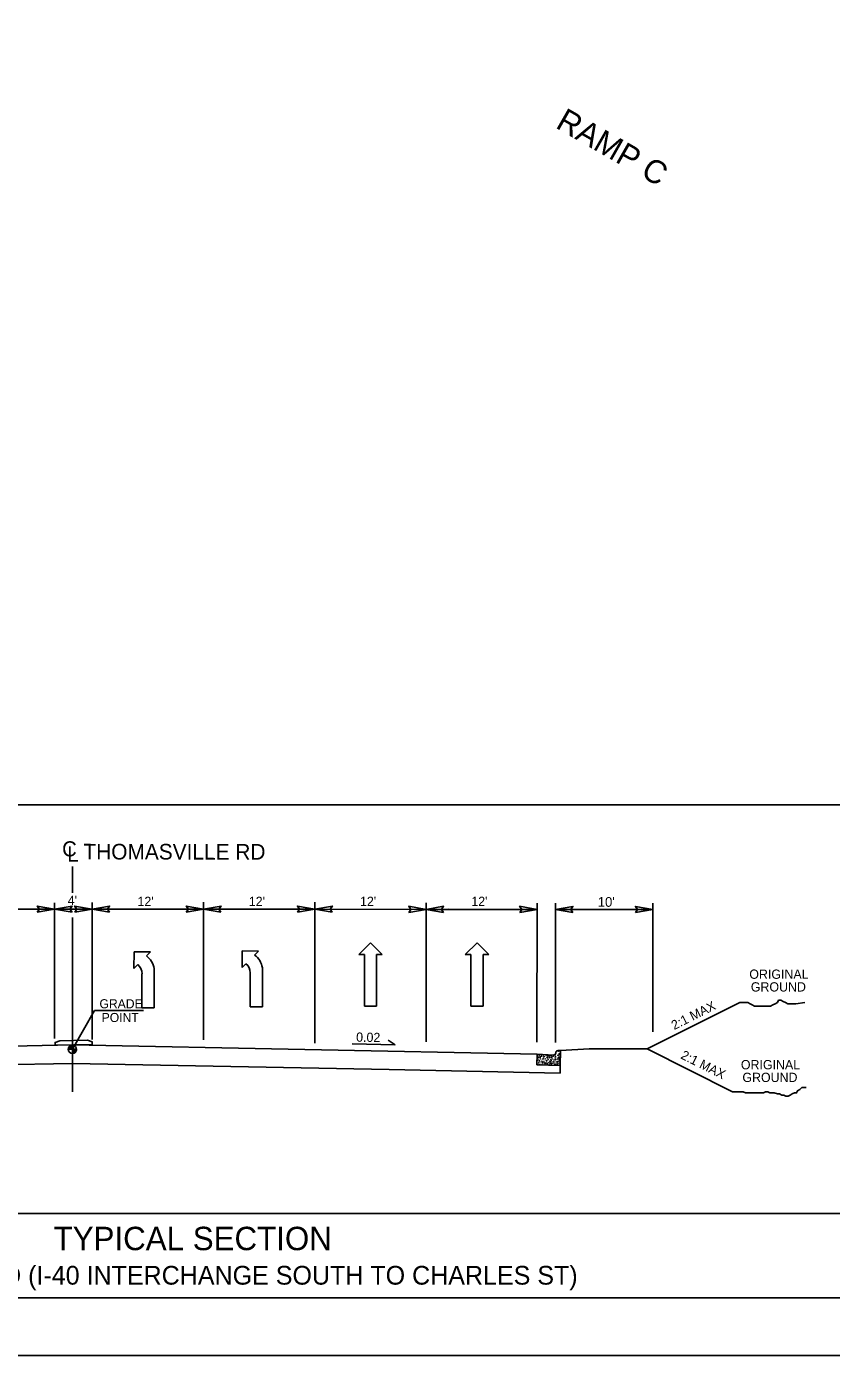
# Model space of a CAD drawing. Extents: x 1636954 to 1644154, y 841334 to 845582.
# Drawn here: x 1640076 to 1640773, y 841334 to 842484 of the extents above; entities that cross this region are included whole.
import ezdxf

# ---------------------------------------------------------------- set-up
doc = ezdxf.new("R2010")
doc.units = 0
for name, color, linetype in [('Default', 7, 'Continuous'), ('Exist Roads EOT Text', 7, 'Continuous'), ('Prop Dimension', 7, 'Continuous'), ('Prop Lane Lines', 7, 'Continuous'), ('Prop PHM Legend CELL', 7, 'Continuous'), ('Scratch_Level_1', 7, 'Continuous'), ('Sheet Plan And Profile CELL', 7, 'Continuous'), ('Typical Curb CELL', 7, 'Continuous'), ('Typical Grade Point Symbol CELL', 7, 'Continuous'), ('Typical Hinge Slope Arterial CELL', 7, 'Continuous'), ('Typical Hinge Slope Interstate CELL', 7, 'Continuous'), ('Typical Pavement Slope CELL', 7, 'Continuous'), ('Typical Pavement Slope Information CELL', 7, 'Continuous'), ('Typical Shoulder Slope CELL', 7, 'Continuous'), ('Typical Text Centerline CELL', 7, 'Continuous'), ('Typical Text General CELL', 7, 'Continuous'), ('Typical Text Grade Point CELL', 7, 'Continuous'), ('Typical Text Label CELL', 7, 'Continuous')]:
    doc.layers.add(name, color=color, linetype=linetype)

msp = doc.modelspace()

# ---------------------------------------------------------------- linework, layer by layer
at = {"layer": 'Default'}
for p, q in [((1640169.3, 841683.2), (1640169.1, 841668.8)), ((1640183.4, 841683.1), (1640169.3, 841683.2)), ((1640180, 841679.7), (1640183.4, 841683.1)), ((1640262.8, 841683.9), (1640262.7, 841669.5)), ((1640276.9, 841683.7), (1640262.8, 841683.9)), ((1640273.6, 841680.4), (1640276.9, 841683.7)), ((1640169.1, 841668.8), (1640172.5, 841672.2)), ((1640176.1, 841664.2), (1640176.1, 841634.8)), ((1640186.7, 841634.8), (1640186.7, 841668.6)), ((1640262.7, 841669.5), (1640266, 841672.8)), ((1640269.7, 841664.8), (1640269.7, 841635.5)), ((1640280.3, 841635.5), (1640280.3, 841669.3)), ((1640176.1, 841634.8), (1640186.7, 841634.8)), ((1640269.7, 841635.5), (1640280.3, 841635.5))]:
    msp.add_line(p, q, dxfattribs=at)
msp.add_lwpolyline([(1640101, 841602.3), (1640101, 841604.7), (1640105, 841606.2), (1640129, 841606.7), (1640133, 841605.3), (1640133, 841603)], close=True, dxfattribs=at)
for centre, radius, start, end in [((1640170.1, 841666.1), 16.8, 8.6761, 53.9878), ((1640263.7, 841666.8), 16.8, 8.6761, 53.9878), ((1640165.7, 841664.2), 10.5, 0, 49.6582), ((1640259.3, 841664.9), 10.5, 0, 49.6582)]:
    msp.add_arc(centre, radius, start, end, dxfattribs=at)
at = {"layer": 'Prop Dimension'}
for p, q in [((1640004.4, 841720), (1640100.6, 841720)), ((1640100.6, 841608.3), (1640100.6, 841725.5)), ((1640100.6, 841720), (1640133, 841720)), ((1640133, 841607.4), (1640133, 841725.9)), ((1640133, 841720), (1640229.5, 841720)), ((1640229.5, 841607), (1640229.5, 841726.2)), ((1640229.5, 841720), (1640325.7, 841720)), ((1640325.7, 841604.1), (1640325.7, 841726.1)), ((1640422, 841719.9), (1640325.7, 841720)), ((1640422, 841725.4), (1640421.9, 841605.2)), ((1640517.9, 841605.1), (1640518, 841725.3)), ((1640533.8, 841604.6), (1640533.9, 841725.3)), ((1640618.2, 841719.8), (1640533.9, 841719.8)), ((1640618.2, 841725.2), (1640618.1, 841614)), ((1640374, 841691), (1640363.8, 841680.9)), ((1640384, 841680.9), (1640374, 841691)), ((1640466.2, 841691), (1640455.9, 841680.9)), ((1640476.1, 841680.9), (1640466.2, 841691)), ((1640363.8, 841680.9), (1640368.6, 841680.9)), ((1640368.6, 841680.9), (1640368.6, 841636)), ((1640379.1, 841636), (1640379.1, 841680.9)), ((1640379.1, 841680.9), (1640384, 841680.9)), ((1640455.9, 841680.9), (1640460.7, 841680.9)), ((1640460.7, 841680.9), (1640460.7, 841636)), ((1640471.3, 841636), (1640471.3, 841680.9)), ((1640471.3, 841680.9), (1640476.1, 841680.9)), ((1640368.6, 841636), (1640379.1, 841636)), ((1640460.7, 841636), (1640471.3, 841636))]:
    msp.add_line(p, q, dxfattribs=at)
for points in [[(1640085.6, 841717.4), (1640100.6, 841720), (1640085.5, 841722.7), (1640087.4, 841720)], [(1640115.7, 841717.4), (1640100.6, 841720), (1640115.7, 841722.7), (1640113.8, 841720)], [(1640118, 841717.4), (1640133, 841720), (1640117.9, 841722.7), (1640119.9, 841720)], [(1640148.1, 841717.4), (1640133, 841720), (1640148.2, 841722.7), (1640146.2, 841720)], [(1640214.4, 841717.4), (1640229.5, 841720), (1640214.4, 841722.7), (1640216.3, 841720)], [(1640244.5, 841717.4), (1640229.5, 841720), (1640244.6, 841722.7), (1640242.7, 841720)], [(1640310.7, 841717.4), (1640325.7, 841720), (1640310.6, 841722.7), (1640312.5, 841720)], [(1640340.8, 841717.4), (1640325.7, 841720), (1640340.9, 841722.7), (1640338.9, 841720)], [(1640407, 841717.3), (1640422, 841719.9), (1640406.9, 841722.6), (1640408.8, 841719.9)], [(1640437, 841717.3), (1640422, 841719.9), (1640437.1, 841722.6), (1640435.2, 841719.9)], [(1640503, 841717.3), (1640518, 841719.9), (1640502.9, 841722.6), (1640504.8, 841719.9)], [(1640548.9, 841717.2), (1640533.9, 841719.8), (1640549, 841722.5), (1640547.1, 841719.8)], [(1640603.1, 841717.2), (1640618.2, 841719.8), (1640603, 841722.5), (1640605, 841719.8)]]:
    msp.add_lwpolyline(points, close=True, dxfattribs=at)
msp.add_lwpolyline([(1640518, 841719.9), (1640422, 841719.9), (1640441, 841720)], dxfattribs=at)
at = {"layer": 'Prop PHM Legend CELL'}
msp.add_line((1637654.2, 841456.6), (1640851.7, 841456.6), dxfattribs=at)
msp.add_lwpolyline([(1639599.4, 841810.2), (1640851.7, 841810.2), (1640851.7, 841383.9), (1639599.4, 841383.9)], close=True, dxfattribs=at)
at = {"layer": 'Scratch_Level_1'}
msp.add_lwpolyline([(1636954.2, 841333.9), (1636954.2, 844733.9), (1644154.2, 844733.9), (1644154.2, 841333.9)], close=True, dxfattribs=at)
at = {"layer": 'Sheet Plan And Profile CELL'}
msp.add_lwpolyline([(1637004.2, 841383.9), (1637004.2, 844683.9), (1644104.2, 844683.9), (1644104.2, 841383.9)], close=True, dxfattribs=at)
at = {"layer": 'Typical Curb CELL'}
for p, q in [((1640517.9, 841585.3), (1640518.1, 841594.6)), ((1640518.1, 841594.6), (1640532.1, 841593.8)), ((1640534.1, 841595.7), (1640534.1, 841595.8)), ((1640538.2, 841597.7), (1640536.1, 841597.7)), ((1640536.6, 841595), (1640536.7, 841594.3)), ((1640537.8, 841594.6), (1640536.6, 841595)), ((1640536.7, 841594.3), (1640537.8, 841594.6)), ((1640538, 841584.9), (1640538.2, 841597.7)), ((1640538, 841584.9), (1640517.9, 841585.3)), ((1640520.1, 841591.8), (1640520.8, 841592.8)), ((1640521.1, 841591.9), (1640520.1, 841591.8)), ((1640520.8, 841592.8), (1640521.1, 841591.9)), ((1640522.3, 841586.7), (1640522.8, 841587.6)), ((1640523.6, 841587), (1640522.3, 841586.7)), ((1640522.8, 841587.6), (1640523.6, 841587)), ((1640526.3, 841591.3), (1640526.8, 841592.3)), ((1640527.6, 841591.6), (1640526.3, 841591.3)), ((1640526.8, 841592.3), (1640527.6, 841591.6)), ((1640528.7, 841588), (1640529.3, 841588.9)), ((1640530.1, 841588.3), (1640528.7, 841588)), ((1640529.3, 841588.9), (1640530.1, 841588.3)), ((1640530.1, 841591.7), (1640530.8, 841592.6)), ((1640531.1, 841591.7), (1640530.1, 841591.7)), ((1640530.8, 841592.6), (1640531.1, 841591.7)), ((1640535.2, 841587.6), (1640535.7, 841588.5)), ((1640536.5, 841587.9), (1640535.2, 841587.6)), ((1640535.7, 841588.5), (1640536.5, 841587.9)), ((1640536.3, 841591.2), (1640536.8, 841592.1)), ((1640537.6, 841591.5), (1640536.3, 841591.2)), ((1640536.8, 841592.1), (1640537.6, 841591.5))]:
    msp.add_line(p, q, dxfattribs=at)
for centre in [(1640518.3, 841593.4), (1640518.8, 841593.2), (1640519.7, 841594.1), (1640520.4, 841593.4), (1640520.8, 841594.3), (1640522, 841593.7), (1640522.2, 841592.9), (1640523.6, 841593.6), (1640523.8, 841594), (1640525.8, 841593.7), (1640526.8, 841593.3), (1640528.3, 841593.3), (1640528.8, 841593), (1640529.7, 841593.7), (1640530.4, 841593.3), (1640532, 841593.6), (1640533.7, 841593.4), (1640533.8, 841593.8), (1640535.9, 841593.6), (1640536.3, 841597.1), (1640536.8, 841593.1), (1640537.6, 841595.3), (1640538.1, 841596.8), (1640518.1, 841590.2), (1640518.2, 841592.7), (1640518.6, 841591.5), (1640518.7, 841585.6), (1640518.9, 841589.2), (1640519.4, 841591.9), (1640519.4, 841587.6), (1640519.7, 841586.3), (1640519.8, 841590), (1640520.1, 841585.4), (1640520.3, 841588.9), (1640520.4, 841587.8), (1640521.1, 841590.5), (1640521.6, 841588.6), (1640521.5, 841585.9), (1640522.7, 841590.3), (1640522.9, 841585.5), (1640523, 841588.4), (1640523.4, 841592.2), (1640523.6, 841591), (1640524.1, 841590), (1640524.1, 841585.4), (1640524.2, 841587.8), (1640524.4, 841592.4), (1640524.7, 841586.7), (1640525.2, 841587), (1640525.5, 841590.5), (1640525.7, 841586), (1640525.9, 841588.9), (1640526.1, 841587.7), (1640526.6, 841586.7), (1640526.9, 841590.2), (1640526.9, 841589.1), (1640527.1, 841585.8), (1640528, 841587.2), (1640528.2, 841592.5), (1640528.1, 841590), (1640528.6, 841591.4), (1640528.8, 841586), (1640529.4, 841586.9), (1640529.4, 841591.7), (1640529.8, 841589.8), (1640530.2, 841585.8), (1640530.6, 841586.7), (1640530.7, 841589.2), (1640531.1, 841590.4), (1640531.1, 841588), (1640531.7, 841586.5), (1640532.2, 841592.8), (1640532.3, 841588.5), (1640532.6, 841587.2), (1640532.7, 841590.1), (1640533, 841586.3), (1640533.4, 841592.1), (1640533.3, 841588.7), (1640533.7, 841590.8), (1640534.1, 841589.9), (1640534.1, 841585.8), (1640534.4, 841592.3), (1640534.5, 841586.8), (1640535.5, 841585.5), (1640535.5, 841590.4), (1640535.8, 841586.4), (1640536.9, 841590), (1640537.1, 841586.3), (1640537.1, 841588.7), (1640537.6, 841587.6)]:
    msp.add_circle(centre, 0.0643, dxfattribs=at)
for centre, start, end in [((1640532.2, 841595.7), 266.7341, 359.1186), ((1640536.1, 841595.8), 89.1186, 179.1186)]:
    msp.add_arc(centre, 1.92, start, end, dxfattribs=at)
at = {"layer": 'Typical Grade Point Symbol CELL'}
for p, q in [((1640112.4, 841598.8), (1640116, 841598.8)), ((1640116, 841598.8), (1640116, 841602.4)), ((1640116, 841595.2), (1640116, 841598.8)), ((1640119.5, 841598.8), (1640116, 841598.8)), ((1640116, 841598.8), (1640116, 841595.2))]:
    msp.add_line(p, q, dxfattribs=at)
for points in [[(1640112.4, 841599.3), (1640112.4, 841598.8)], [(1640112.5, 841599.7), (1640112.5, 841598.8)], [(1640112.6, 841600.1), (1640112.6, 841598.8)], [(1640112.6, 841599.9), (1640112.6, 841598.8)], [(1640112.7, 841600.3), (1640112.7, 841598.8)], [(1640112.8, 841600.6), (1640112.8, 841598.8)], [(1640112.8, 841600.5), (1640112.8, 841598.8)], [(1640112.9, 841600.7), (1640112.9, 841598.8)], [(1640113, 841600.8), (1640113, 841598.8)], [(1640113.1, 841601), (1640113.1, 841598.8)], [(1640113.1, 841600.9), (1640113.1, 841598.8)], [(1640113.2, 841601.1), (1640113.2, 841598.8)], [(1640113.3, 841601.3), (1640113.3, 841598.8)], [(1640113.3, 841601.2), (1640113.3, 841598.8)], [(1640113.4, 841601.4), (1640113.4, 841598.8)], [(1640113.5, 841601.4), (1640113.5, 841598.8)], [(1640113.6, 841601.6), (1640113.6, 841598.8)], [(1640113.6, 841601.5), (1640113.6, 841598.8)], [(1640113.7, 841601.6), (1640113.7, 841598.8)], [(1640113.8, 841601.7), (1640113.8, 841598.8)], [(1640113.8, 841601.7), (1640113.8, 841598.8)], [(1640113.9, 841601.8), (1640113.9, 841598.8)], [(1640114, 841601.8), (1640114, 841598.8)], [(1640114.1, 841601.9), (1640114.1, 841598.8)], [(1640114.1, 841601.9), (1640114.1, 841598.8)], [(1640114.2, 841602), (1640114.2, 841598.8)], [(1640114.3, 841602), (1640114.3, 841598.8)], [(1640114.3, 841602), (1640114.3, 841598.8)], [(1640114.4, 841602.1), (1640114.4, 841598.8)], [(1640114.5, 841602.1), (1640114.5, 841598.8)], [(1640114.6, 841602.2), (1640114.6, 841598.8)], [(1640114.6, 841602.1), (1640114.6, 841598.8)], [(1640114.7, 841602.2), (1640114.7, 841598.8)], [(1640114.8, 841602.2), (1640114.8, 841598.8)], [(1640114.8, 841602.2), (1640114.8, 841598.8)], [(1640114.9, 841602.3), (1640114.9, 841598.8)], [(1640115, 841602.3), (1640115, 841598.8)], [(1640115.1, 841602.3), (1640115.1, 841598.8)], [(1640115.1, 841602.3), (1640115.1, 841598.8)], [(1640115.2, 841602.3), (1640115.2, 841598.8)], [(1640115.3, 841602.4), (1640115.3, 841598.8)], [(1640115.3, 841602.3), (1640115.3, 841598.8)], [(1640115.4, 841602.4), (1640115.4, 841598.8)], [(1640115.5, 841602.4), (1640115.5, 841598.8)], [(1640115.6, 841602.4), (1640115.6, 841598.8)], [(1640115.6, 841602.4), (1640115.6, 841598.8)], [(1640115.7, 841602.4), (1640115.7, 841598.8)], [(1640115.8, 841602.4), (1640115.8, 841598.8)], [(1640115.9, 841602.4), (1640115.9, 841602.4), (1640115.9, 841598.8)], [(1640115.9, 841602.4), (1640115.9, 841598.8)], [(1640116, 841598.8), (1640116, 841595.2), (1640116, 841595.2)], [(1640116.1, 841598.8), (1640116.1, 841595.2)], [(1640116.2, 841598.8), (1640116.2, 841595.2)], [(1640116.2, 841598.8), (1640116.2, 841595.2)], [(1640116.3, 841598.8), (1640116.3, 841595.3)], [(1640116.4, 841598.8), (1640116.4, 841595.3)], [(1640116.4, 841598.8), (1640116.4, 841595.3)], [(1640116.5, 841598.8), (1640116.5, 841595.3)], [(1640116.6, 841598.8), (1640116.6, 841595.3)], [(1640116.7, 841598.8), (1640116.7, 841595.3)], [(1640116.7, 841598.8), (1640116.7, 841595.3)], [(1640116.8, 841598.8), (1640116.8, 841595.3)], [(1640116.9, 841598.8), (1640116.9, 841595.4)], [(1640116.9, 841598.8), (1640116.9, 841595.4)], [(1640117, 841598.8), (1640117, 841595.4)], [(1640117.1, 841598.8), (1640117.1, 841595.4)], [(1640117.2, 841598.8), (1640117.2, 841595.5)], [(1640117.2, 841598.8), (1640117.2, 841595.4)], [(1640117.3, 841598.8), (1640117.3, 841595.5)], [(1640117.4, 841598.8), (1640117.4, 841595.6)], [(1640117.4, 841598.8), (1640117.4, 841595.5)], [(1640117.5, 841598.8), (1640117.5, 841595.6)], [(1640117.6, 841598.8), (1640117.6, 841595.6)], [(1640117.7, 841598.8), (1640117.7, 841595.7)], [(1640117.7, 841598.8), (1640117.7, 841595.7)], [(1640117.8, 841598.8), (1640117.8, 841595.7)], [(1640117.9, 841598.8), (1640117.9, 841595.8)], [(1640117.9, 841598.8), (1640117.9, 841595.8)], [(1640118, 841598.8), (1640118, 841595.9)], [(1640118.1, 841598.8), (1640118.1, 841595.9)], [(1640118.2, 841598.8), (1640118.2, 841596.1)], [(1640118.2, 841598.8), (1640118.2, 841596)], [(1640118.3, 841598.8), (1640118.3, 841596.1)], [(1640118.4, 841598.8), (1640118.4, 841596.2)], [(1640118.5, 841598.8), (1640118.5, 841596.3)], [(1640118.5, 841598.8), (1640118.5, 841596.2)], [(1640118.6, 841598.8), (1640118.6, 841596.4)], [(1640118.7, 841598.8), (1640118.7, 841596.6)], [(1640118.7, 841598.8), (1640118.7, 841596.5)], [(1640118.8, 841598.8), (1640118.8, 841596.6)], [(1640118.9, 841598.8), (1640118.9, 841596.7)], [(1640119, 841598.8), (1640119, 841597)], [(1640119, 841598.8), (1640119, 841596.8)], [(1640119.1, 841598.8), (1640119.1, 841597.1)], [(1640119.2, 841598.8), (1640119.2, 841597.4)], [(1640119.2, 841598.8), (1640119.2, 841597.2)], [(1640119.3, 841598.8), (1640119.3, 841597.5)], [(1640119.4, 841598.8), (1640119.4, 841597.8)], [(1640119.5, 841598.8), (1640119.5, 841598.4)], [(1640119.5, 841598.8), (1640119.5, 841598)]]:
    msp.add_lwpolyline(points, dxfattribs=at)
msp.add_circle((1640116, 841598.8), 3.59, dxfattribs=at)
for start, end in [(90.0093, 180.0093), (270.0093, 0.0093)]:
    msp.add_arc((1640116, 841598.8), 3.59, start, end, dxfattribs=at)
at = {"layer": 'Typical Hinge Slope Arterial CELL'}
msp.add_lwpolyline([(1640749.6, 841639.2), (1640741.7, 841638.2), (1640739.7, 841638.2), (1640736.7, 841638.2), (1640734.8, 841638.2), (1640732.8, 841639.2), (1640730.8, 841640.2), (1640728.8, 841641.2), (1640726.9, 841641.2), (1640725.9, 841639.2), (1640723.9, 841638.2), (1640721.9, 841637.2), (1640720, 841636.2), (1640718, 841636.2), (1640716, 841636.2), (1640714, 841636.2), (1640712.1, 841636.2), (1640710.1, 841636.2), (1640708.1, 841636.2), (1640706.1, 841636.2), (1640704.2, 841637.2), (1640702.2, 841638.2), (1640700.2, 841639.2), (1640697.2, 841639.2), (1640695.3, 841639.2), (1640693.3, 841639.2)], dxfattribs=at)
at = {"layer": 'Typical Hinge Slope Interstate CELL'}
for p, q in [((1640693.3, 841639.2), (1640613.1, 841599.1)), ((1640613.1, 841599.1), (1640687.1, 841562))]:
    msp.add_line(p, q, dxfattribs=at)
msp.add_lwpolyline([(1640750.8, 841565.7), (1640749, 841565.7), (1640747.1, 841565.7), (1640745.3, 841563.9), (1640743.4, 841562.9), (1640742.5, 841561.1), (1640740.7, 841561.1), (1640738.8, 841560.2), (1640737, 841559.2), (1640735.1, 841558.3), (1640733.3, 841558.3), (1640731.4, 841559.2), (1640729.6, 841559.2), (1640727.7, 841560.2), (1640725.9, 841560.2), (1640723.1, 841561.1), (1640721.3, 841561.1), (1640719.4, 841561.1), (1640717.6, 841562), (1640715.7, 841562), (1640713.9, 841561.1), (1640712, 841561.1), (1640710.2, 841561.1), (1640708.3, 841561.1), (1640706.5, 841561.1), (1640703.7, 841561.1), (1640700.9, 841561.1), (1640698.2, 841561.1), (1640696.3, 841562), (1640693.5, 841562), (1640690.8, 841562), (1640687.1, 841562)], dxfattribs=at)
at = {"layer": 'Typical Pavement Slope CELL'}
for p, q in [((1639908.1, 841598.5), (1640116, 841602.6)), ((1640518.1, 841594.6), (1640116, 841602.7)), ((1639888.4, 841582.1), (1640116, 841586.6)), ((1640390, 841581.2), (1640116, 841586.6)), ((1640537.9, 841578.2), (1640538, 841584.9)), ((1640537.9, 841578.2), (1640390, 841581.2))]:
    msp.add_line(p, q, dxfattribs=at)
at = {"layer": 'Typical Pavement Slope Information CELL'}
for q in [(1640389.1, 841606.6), (1640358, 841603.6)]:
    msp.add_line((1640395.3, 841602.8), q, dxfattribs=at)
at = {"layer": 'Typical Shoulder Slope CELL'}
for p, q in [((1640538.2, 841597.7), (1640563, 841599.1)), ((1640563, 841599.1), (1640613.1, 841599.1))]:
    msp.add_line(p, q, dxfattribs=at)
at = {"layer": 'Typical Text Centerline CELL'}
for p, q in [((1640116, 841734.3), (1640116, 841757.1)), ((1640116, 841561.9), (1640116, 841712.9))]:
    msp.add_line(p, q, dxfattribs=at)
at = {"layer": 'Typical Text Grade Point CELL'}
for q in [(1640116, 841598.8), (1640177.5, 841632.4)]:
    msp.add_line((1640135, 841632.4), q, dxfattribs=at)

# ---------------------------------------------------------------- texts
at = {"layer": 'Exist Roads EOT Text'}
msp.add_text('RAMP C', height=20, rotation=330.2753, dxfattribs=at).set_placement((1640533.1, 842396.6))
at = {"layer": 'Prop Dimension'}
msp.add_text("10'", height=8.44, rotation=360, dxfattribs=at).set_placement((1640570.5, 841722.1))
at = {"layer": 'Prop Lane Lines'}
for s, p in [('ORIGINAL', (1640701.6, 841659.8)), ('GROUND', (1640702.9, 841648.8)), ('ORIGINAL', (1640694.3, 841581.5)), ('GROUND', (1640695.6, 841570.5))]:
    msp.add_text(s, height=8.02, dxfattribs=at).set_placement(p)
at = {"layer": 'Typical Hinge Slope Interstate CELL'}
for rotation, p in [(26.5646, (1640636.6, 841615.4)), (333.4354, (1640641.6, 841591.2))]:
    msp.add_text('2:1 MAX', height=8.02, rotation=rotation, dxfattribs=at).set_placement(p)
at = {"layer": 'Typical Pavement Slope Information CELL'}
for s, p in [("4'", (1640112, 841723.7)), ("12'", (1640172.3, 841722.8)), ("12'", (1640268.6, 841722.8)), ("12'", (1640364.8, 841722.8)), ("12'", (1640461.1, 841722.8))]:
    msp.add_text(s, height=8.02, dxfattribs=at).set_placement(p)
msp.add_text('0.02', height=8.02, rotation=358.8543, dxfattribs=at).set_placement((1640361.4, 841605.4))
at = {"layer": 'Typical Text Centerline CELL'}
for s, height, rotation, p in [('C', 13.1, 0.0443, (1640107.1, 841765.7)), ('L', 13.2, 359.9912, (1640111.5, 841761.2)), ('THOMASVILLE RD', 13.5, 359.9417, (1640125.5, 841763.1))]:
    msp.add_text(s, height=height, rotation=rotation, dxfattribs=at).set_placement(p)
at = {"layer": 'Typical Text General CELL'}
msp.add_text('-Y1- THOMASVILLE RD (I-40 INTERCHANGE SOUTH TO CHARLES ST)', height=16.2, dxfattribs=at).set_placement((1639835.7, 841395.2))
at = {"layer": 'Typical Text Grade Point CELL'}
for s, p in [('GRADE', (1640139.4, 841634.3)), ('POINT', (1640141.3, 841622.4))]:
    msp.add_text(s, height=7.85, rotation=359.9998, dxfattribs=at).set_placement(p)
at = {"layer": 'Typical Text Label CELL'}
msp.add_text('TYPICAL SECTION', height=20.25, dxfattribs=at).set_placement((1640099.7, 841425))

doc.saveas('drawing.dxf')
